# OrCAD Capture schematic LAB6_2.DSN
size A
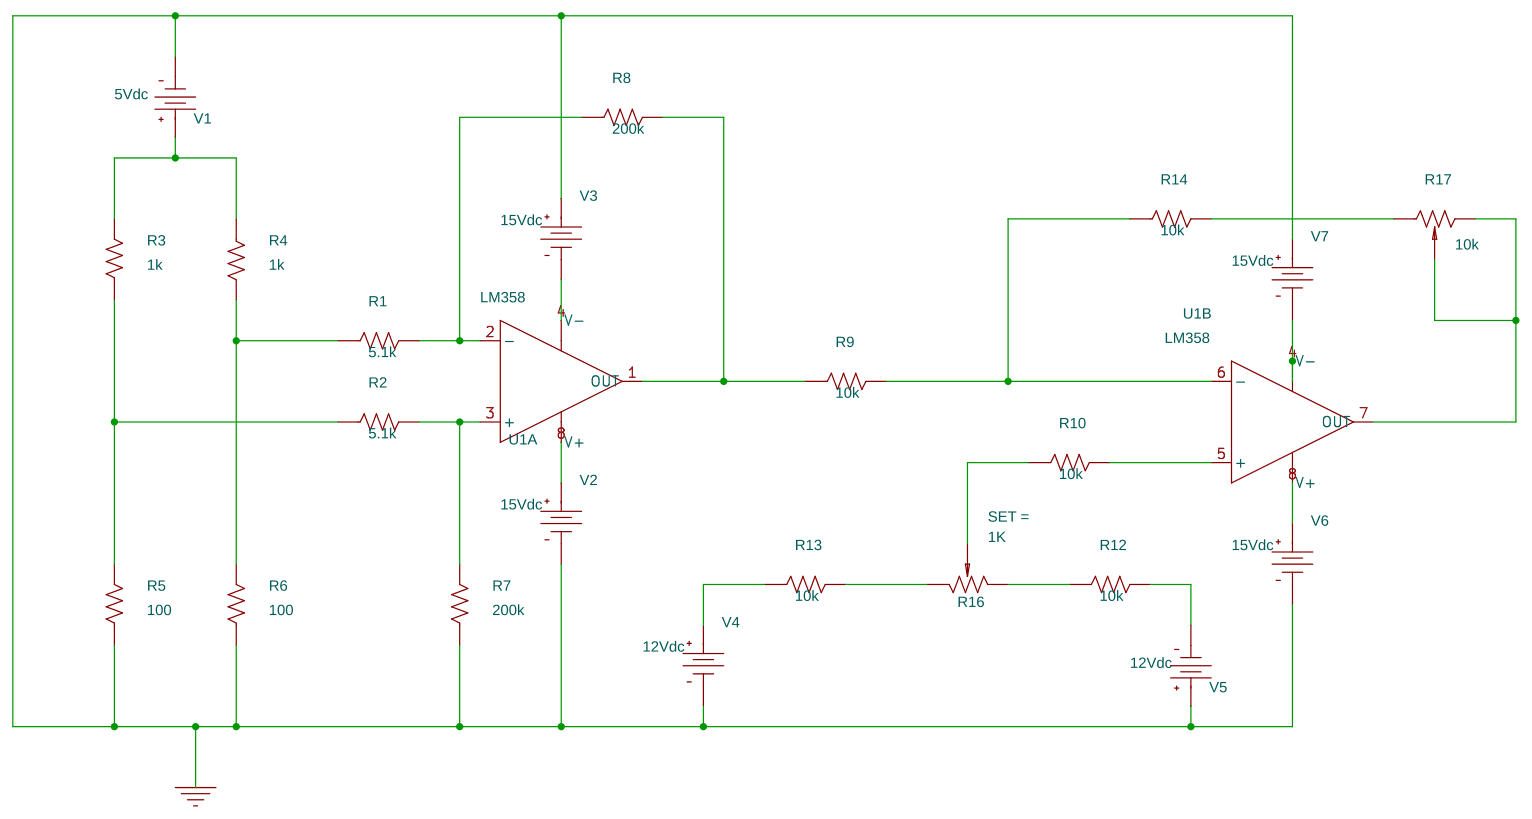
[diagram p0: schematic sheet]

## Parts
R1  5.1k  [AXRC05]
R2  5.1k  [AXRC05]
R3  1k  [AXRC05]
R4  1k  [AXRC05]
R5  100  [AXRC05]
R6  100  [AXRC05]
R7  200k  [AXRC05]
R8  200k  [AXRC05]
R9  10k  [AXRC05]
R10  10k  [AXRC05]
R12  10k  [AXRC05]
R13  10k  [AXRC05]
R14  10k  [AXRC05]
R16  1K  [VRES10]
R17  10k  [VRES10]
U1  LM358  [DIP1008W300L450]  (sections A,B)
V1  VDC
V2  VDC
V3  VDC
V4  VDC
V5  VDC
V6  VDC
V7  VDC

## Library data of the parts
R1-R10 R12-R14 = R
R16 R17 = POT
U1 = LM358
V1 = VDC: DC: 5Vdc
V2 V3 V6 V7 = VDC: DC: 15Vdc
V4 V5 = VDC: DC: 12Vdc

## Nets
0: R5.1 R6.1 R7.1 V1.1(-) V2.1(-) V3.0(+) V4.1(-) V5.0(+) V6.1(-) V7.0(+)
N00500: R2.1 R3.1 R5.2
N00526: R1.1 R4.2 R6.2
N00530: R3.2 R4.1 V1.0(+)
N00601: R2.2 R7.2 U1.3(+)
N00605: R1.2 R8.1 U1.2(-)
N00669: U1.8(V+) V2.0(+) V6.0(+)
N00740: U1.4(V-) V3.1(-) V7.1(-)
N00778: R8.2 R9.1 U1.1(OUT)
N00817: R9.2 R14.1 U1.6(-)
N00834: R14.2 R17.1
N00838: R17.2(t) R17.3(2) U1.7(OUT)
N00991: R13.1 V4.0(+)
N00998: R13.2 R16.1
N01006: R12.2 V5.1(-)
N01035: R10.2 U1.5(+)
N01039: R10.1 R16.2(t)
N02185: R12.1 R16.3(2)
